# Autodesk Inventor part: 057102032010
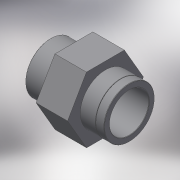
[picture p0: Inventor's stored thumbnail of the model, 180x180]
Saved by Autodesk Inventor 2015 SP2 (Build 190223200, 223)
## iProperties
Created: 2017-10
Part Number: 057102032010
Material: Generic
Description: PLASSON AD. SOCKET REINF.PVC 32-1"
Document SubType Name: Modeling
Designer: KIM
Density: 1 g/cm^3
Appearance: Default
Author: KIM
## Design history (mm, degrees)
derived "057102.ipt"
feature "Solid1::057102.ipt"
tag "TaggingFeature1"
body "Solid1"
other parameters: "d0" = 45, "d1" = 32, "d2" = 45, "d3" = 30.291, "d4" = 28.8, "d5" = 22, "d7" = 38.4, "d8" = 36.8, "d10" = 14, "d13" = 0, "d14" = 0.32, "d15" = 12, "d16" = 5, "d17" = 38.4, "d18" = 0.1, "d_" = 32, "G_" = 30.291, "C_" = 45, "B_" = 12, "l_" = 22, "H_" = 45
